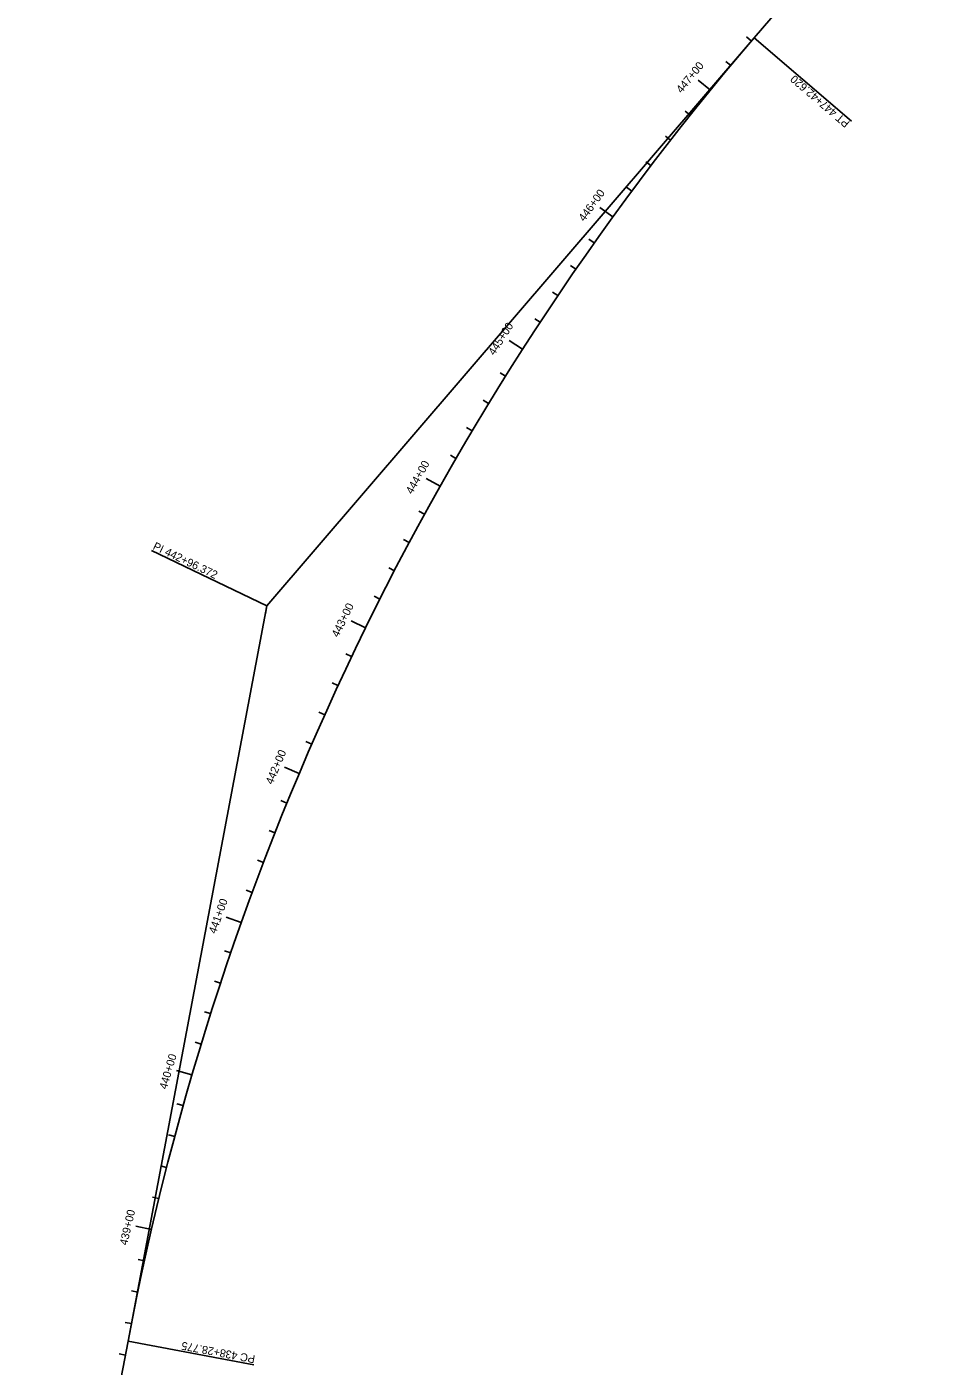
# Model space of a CAD drawing. Extents: x 187748 to 191086, y 249974 to 259749.
# Drawn here: x 188532 to 189107, y 250762 to 251599 of the extents above; entities that cross this region are included whole.
import ezdxf

# ---------------------------------------------------------------- set-up
doc = ezdxf.new("R2010")
doc.units = 0
doc.layers.add('BORDER', color=7, linetype='Continuous')

msp = doc.modelspace()

# ---------------------------------------------------------------- linework, layer by layer
at = {"layer": 'BORDER'}
for p, q in [((188986.39, 251591.84), (189106.96, 251732.43)), ((188984.69, 251589.85), (188981.65, 251592.45)), ((188986.39, 251591.84), (189047.12, 251539.76)), ((188971.78, 251574.57), (188968.71, 251577.14)), ((188959.05, 251559.15), (188951.3, 251565.48)), ((188946.49, 251543.59), (188943.36, 251546.08)), ((188934.11, 251527.88), (188930.95, 251530.33)), ((188921.91, 251512.03), (188918.73, 251514.45)), ((188909.9, 251496.04), (188906.68, 251498.43)), ((188898.06, 251479.92), (188889.97, 251485.79)), ((188886.41, 251463.66), (188883.15, 251465.97)), ((188874.95, 251447.27), (188871.66, 251449.54)), ((188863.68, 251430.75), (188860.36, 251432.98)), ((188852.6, 251414.1), (188849.25, 251416.3)), ((188841.7, 251397.33), (188833.29, 251402.73)), ((188831, 251380.43), (188827.61, 251382.55)), ((188820.5, 251363.41), (188817.08, 251365.49)), ((188810.19, 251346.28), (188806.75, 251348.32)), ((188800.07, 251329.02), (188796.61, 251331.03)), ((188790.15, 251311.65), (188781.44, 251316.56)), ((188780.44, 251294.17), (188776.93, 251296.1)), ((188770.92, 251276.58), (188767.39, 251278.47)), ((188682, 251236.89), (188609.88, 251271.53)), ((188761.6, 251258.89), (188758.05, 251260.73)), ((188752.49, 251241.08), (188748.92, 251242.89)), ((188682, 251236.89), (188681.07, 251231.98)), ((188682, 251236.89), (188685.25, 251240.69)), ((188743.58, 251223.18), (188734.6, 251227.58)), ((188734.88, 251205.17), (188731.27, 251206.89)), ((188726.38, 251187.07), (188722.75, 251188.74)), ((188718.09, 251168.86), (188714.44, 251170.5)), ((188710.01, 251150.57), (188706.34, 251152.17)), ((188702.14, 251132.18), (188692.92, 251136.07)), ((188694.48, 251113.71), (188690.77, 251115.22)), ((188687.03, 251095.15), (188683.31, 251096.62)), ((188679.79, 251076.5), (188676.05, 251077.93)), ((188672.77, 251057.78), (188669.01, 251059.16)), ((188665.96, 251038.97), (188656.54, 251042.32)), ((188659.36, 251020.09), (188655.58, 251021.39)), ((188652.99, 251001.14), (188649.19, 251002.39)), ((188646.83, 250982.11), (188643.01, 250983.32)), ((188640.88, 250963.01), (188637.06, 250964.18)), ((188635.16, 250943.85), (188625.56, 250946.65)), ((188629.66, 250924.62), (188625.8, 250925.7)), ((188624.37, 250905.33), (188620.51, 250906.37)), ((188619.31, 250885.98), (188615.43, 250886.97)), ((188614.47, 250866.58), (188610.58, 250867.52)), ((188609.85, 250847.12), (188600.1, 250849.37)), ((188605.45, 250827.61), (188601.54, 250828.47)), ((188601.28, 250808.05), (188597.36, 250808.86)), ((188597.33, 250788.44), (188593.4, 250789.21)), ((188531.98, 250442.67), (188595.21, 250777.42)), ((188595.21, 250777.42), (188673.82, 250762.57)), ((188593.58, 250768.8), (188589.65, 250769.54))]:
    msp.add_line(p, q, dxfattribs=at)
msp.add_lwpolyline([(188595.21, 250777.42), (188682, 251236.89), (188986.39, 251591.84)], dxfattribs=at)
msp.add_arc((190314.8, 250452.61), 1750, 139.38386, 169.30355, dxfattribs=at)

# ---------------------------------------------------------------- texts
for s, rotation, p in [('447+00', 50.77927, (188941.03, 251556.9)), ('PT 447+42.620', 139.38387, (189046.49, 251539.1)), ('446+00', 54.05331, (188880.21, 251476.68)), ('445+00', 57.32736, (188824.05, 251393.01)), ('444+00', 60.6014, (188772.77, 251306.32)), ('PI 442+96.372', 334.34371, (188610.31, 251272.5)), ('443+00', 63.87545, (188726.54, 251216.88)), ('442+00', 67.14949, (188685.48, 251124.91)), ('441+00', 70.42354, (188650.09, 251031.69)), ('440+00', 73.69758, (188619.39, 250934.5)), ('439+00', 76.97163, (188594.68, 250837.05)), ('PC 438+28.775', 169.30355, (188674.94, 250768.5))]:
    msp.add_text(s, height=5, rotation=rotation, dxfattribs=at).set_placement(p)

doc.saveas('drawing.dxf')
